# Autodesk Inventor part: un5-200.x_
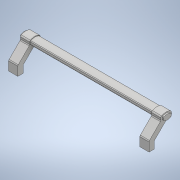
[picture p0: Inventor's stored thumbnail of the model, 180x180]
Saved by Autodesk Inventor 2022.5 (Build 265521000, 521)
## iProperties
Part Number: un5-200.x_
Material: 一般
Document SubType Name: Modeling
Designer: ImaoCorp
Density: 1 g/cm^3
Appearance: 既定
Sending System: SOLIDWORKS 2017-2017317
MC: AMD64
MC_MODEL: Intel64 Family 6 Model 60 Stepping 3, GenuineIntel
OS: Windows_NT
FRU: Parasolid Version 29.0, build 201,  4-17-2017
FORMAT: text
GUISE: transmit
KEY: un5-200
FILE: un5-200.x_t
DATE: Thu Sep 19 11:10:20 2019
Author: ImaoCorp
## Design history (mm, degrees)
feature "Base1"
node "ソリッド1"
